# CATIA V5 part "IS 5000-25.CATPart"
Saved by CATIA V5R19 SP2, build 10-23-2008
Part number: IS 5000-25
Bounding box of the stored display mesh (mm): x -59.975 to 59.975, y -59.975 to 59.975, z 0 to 190
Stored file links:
  C:\Users\Bora\Desktop\3D Katı model\IS serisi\IS 5000\IS 5000-25.CATPart
  C:\Program Files\Dassault Systemes\B19\intel_a\reffiles\standard\MetricThickPitch.txt
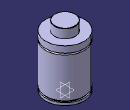
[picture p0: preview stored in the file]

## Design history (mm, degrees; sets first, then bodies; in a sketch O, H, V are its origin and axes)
Body1 (main body)
  Sketch1 on yz-plane, origin (0, 0, 0), H (0, 1, 0), V (0, 0, 1)
    point P1 (60, 142)
    point P4 (60, 137)
    point P7 (32.5, 189)
    point P9 (32.5, 189)
    point P13 (60, 142)
    point P14 (60, 137)
    line L1 (60, 142) -> (60, 162)
    line L2 (60, 13) -> (60, 137)
    line L3 (56, 13) -> (56, 8)
    arc A1 centre (31.5, 189) radius 1 from (32.5, 189) to (31.5, 190) ccw
    line L4 (32.5, 189) -> (32.5, 162)
    line L5 (60, 0) -> (60, 8)
    arc A2 centre (60, 139.5) radius 2.5 from (60, 142) to (60, 137) ccw
    line L6 (31.5, 190) -> (0, 190)
    point P15 (0, 190)
    line L7 (32.5, 162) -> (60, 162)
    line L8 (0, 0) -> (60, 0)
    line L9 (56, 13) -> (60, 13)
    line L10 (56, 8) -> (60, 8)
    coincidence: P15 V, P1 P13, P4 P14, P7 P9
    tangency: L6 A1
    horizontal: L7 H, L8 H, L9 H, L10 H
  Shaft1: profile Sketch1, axis Sketch1.V, angle 360
  Sketch2 on face of Shaft1 from Sketch1.L8, origin (0, 0, 0), H (1, 0, 0), V (0, -1, 0)
    point P1 (40, 0)
    distance P1 V = 40
  Hole1: placed by Sketch2, at (40, 0, 0) direction (0, 0, 1), diameter 8.376, depth 16, threaded "M10", thread diameter 10, thread depth 16, pitch 1.5
  CircPattern1: of Hole1, instances 4, angular step 90, axis from xy-plane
